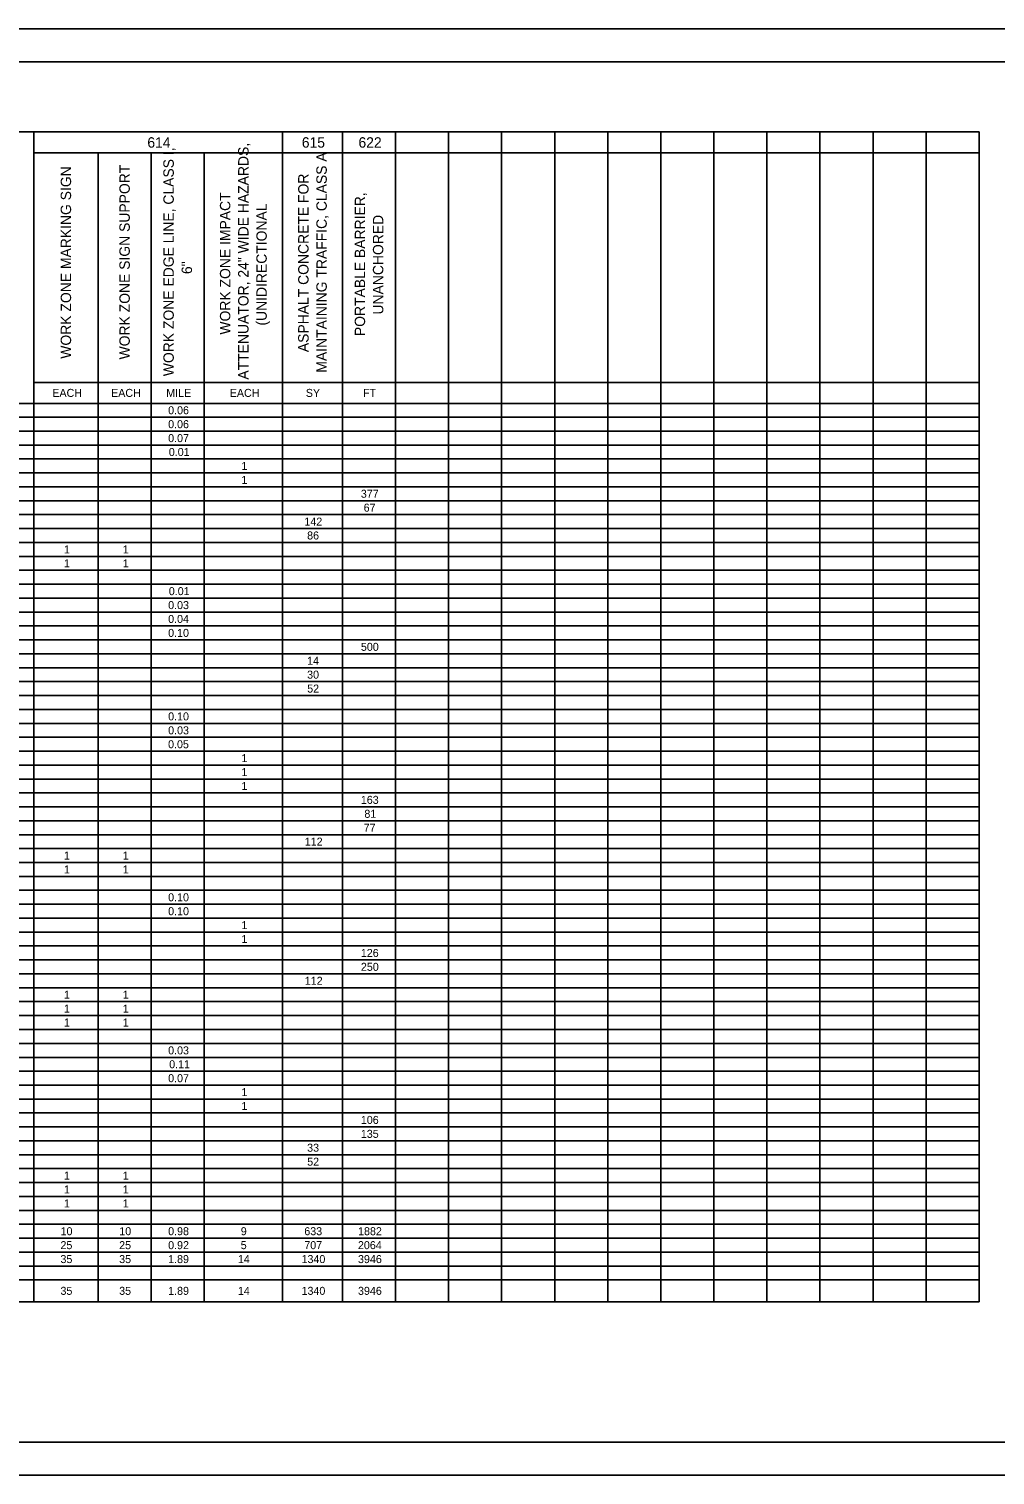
# Model space of a CAD drawing. Extents: x 0 to 37.7, y 0 to 22.
# Drawn here: x 13.5 to 28.19, y 0 to 22 of the extents above; entities that cross this region are included whole.
import ezdxf

# ---------------------------------------------------------------- set-up
doc = ezdxf.new("R2010")
doc.units = 0
for name, color, linetype in [('SH_Border', 7, 'Continuous'), ('SH_Cut_Line', 7, 'Continuous'), ('SH_Text', 7, 'Continuous')]:
    doc.layers.add(name, color=color, linetype=linetype)

msp = doc.modelspace()

# ---------------------------------------------------------------- linework, layer by layer
at = {"layer": 'SH_Border'}
msp.add_lwpolyline([(1.5, 21.5), (33.5, 21.5), (33.5, 0.5), (1.5, 0.5)], close=True, dxfattribs=at)
at = {"layer": 'SH_Cut_Line'}
msp.add_lwpolyline([(0, 0), (34, 0), (34, 22), (0, 22)], close=True, dxfattribs=at)
at = {"layer": 'SH_Text'}
for p, q in [((6.664, 20.432), (27.951, 20.432)), ((13.57, 20.432), (13.57, 2.638)), ((17.354, 20.432), (17.354, 2.638)), ((18.267, 20.432), (18.267, 2.638)), ((19.074, 20.432), (19.074, 2.638)), ((19.881, 20.432), (19.881, 2.638)), ((20.688, 20.432), (20.688, 2.638)), ((21.495, 20.432), (21.495, 2.638)), ((22.302, 20.432), (22.302, 2.638)), ((23.109, 20.432), (23.109, 2.638)), ((23.916, 20.432), (23.916, 2.638)), ((24.723, 20.432), (24.723, 2.638)), ((25.53, 20.432), (25.53, 2.638)), ((26.337, 20.432), (26.337, 2.638)), ((27.144, 20.432), (27.144, 2.638)), ((27.951, 20.432), (27.951, 2.638)), ((13.57, 20.115), (27.951, 20.115)), ((14.549, 20.115), (14.549, 2.638)), ((15.357, 20.115), (15.357, 2.638)), ((16.164, 20.115), (16.164, 2.638)), ((13.57, 16.622), (27.951, 16.622)), ((6.664, 16.304), (27.951, 16.304)), ((6.664, 16.093), (27.951, 16.093)), ((6.664, 15.881), (27.951, 15.881)), ((6.664, 15.669), (27.951, 15.669)), ((6.664, 15.458), (27.951, 15.458)), ((6.664, 15.246), (27.951, 15.246)), ((6.664, 15.034), (27.951, 15.034)), ((6.664, 14.823), (27.951, 14.823)), ((6.664, 14.611), (27.951, 14.611)), ((6.664, 14.399), (27.951, 14.399)), ((6.664, 14.188), (27.951, 14.188)), ((6.664, 13.976), (27.951, 13.976)), ((6.664, 13.764), (27.951, 13.764)), ((6.664, 13.553), (27.951, 13.553)), ((6.664, 13.341), (27.951, 13.341)), ((6.664, 13.129), (27.951, 13.129)), ((6.664, 12.918), (27.951, 12.918)), ((6.664, 12.706), (27.951, 12.706)), ((6.664, 12.494), (27.951, 12.494)), ((6.664, 12.282), (27.951, 12.282)), ((6.664, 12.071), (27.951, 12.071)), ((6.664, 11.859), (27.951, 11.859)), ((6.664, 11.647), (27.951, 11.647)), ((6.664, 11.436), (27.951, 11.436)), ((6.664, 11.224), (27.951, 11.224)), ((6.664, 11.012), (27.951, 11.012)), ((6.664, 10.801), (27.951, 10.801)), ((6.664, 10.589), (27.951, 10.589)), ((6.664, 10.377), (27.951, 10.377)), ((6.664, 10.166), (27.951, 10.166)), ((6.664, 9.954), (27.951, 9.954)), ((6.664, 9.742), (27.951, 9.742)), ((6.664, 9.531), (27.951, 9.531)), ((6.664, 9.319), (27.951, 9.319)), ((6.664, 9.107), (27.951, 9.107)), ((6.664, 8.896), (27.951, 8.896)), ((6.664, 8.684), (27.951, 8.684)), ((6.664, 8.472), (27.951, 8.472)), ((6.664, 8.261), (27.951, 8.261)), ((6.664, 8.049), (27.951, 8.049)), ((6.664, 7.837), (27.951, 7.837)), ((6.664, 7.626), (27.951, 7.626)), ((6.664, 7.414), (27.951, 7.414)), ((6.664, 7.202), (27.951, 7.202)), ((6.664, 6.99), (27.951, 6.99)), ((6.664, 6.779), (27.951, 6.779)), ((6.664, 6.567), (27.951, 6.567)), ((6.664, 6.355), (27.951, 6.355)), ((6.664, 6.144), (27.951, 6.144)), ((6.664, 5.932), (27.951, 5.932)), ((6.664, 5.72), (27.951, 5.72)), ((6.664, 5.509), (27.951, 5.509)), ((6.664, 5.297), (27.951, 5.297)), ((6.664, 5.085), (27.951, 5.085)), ((6.664, 4.874), (27.951, 4.874)), ((6.664, 4.662), (27.951, 4.662)), ((6.664, 4.45), (27.951, 4.45)), ((6.664, 4.239), (27.951, 4.239)), ((6.664, 4.027), (27.951, 4.027)), ((6.664, 3.815), (27.951, 3.815)), ((6.664, 3.604), (27.951, 3.604)), ((6.664, 3.392), (27.951, 3.392)), ((6.664, 3.18), (27.951, 3.18)), ((6.664, 2.969), (27.951, 2.969)), ((6.664, 2.638), (27.951, 2.638))]:
    msp.add_line(p, q, dxfattribs=at)

# ---------------------------------------------------------------- texts
for s, height, p in [('614', 0.1582, (15.299, 20.194)), ('615', 0.1582, (17.648, 20.194)), ('622', 0.1582, (18.51, 20.194)), ('EACH', 0.1217, (13.853, 16.402)), ('EACH', 0.1217, (14.747, 16.402)), ('MILE', 0.1217, (15.586, 16.402)), ('EACH', 0.1217, (16.552, 16.402)), ('SY', 0.1217, (17.709, 16.402)), ('FT', 0.1217, (18.579, 16.402)), ('0.06', 0.1217, (15.615, 16.138)), ('0.06', 0.1217, (15.615, 15.926)), ('0.07', 0.1217, (15.615, 15.714)), ('0.01', 0.1217, (15.625, 15.503)), ('1', 0.122, (16.73, 15.291)), ('1', 0.122, (16.73, 15.079)), ('377', 0.1217, (18.546, 14.868)), ('67', 0.1217, (18.589, 14.656)), ('142', 0.1217, (17.687, 14.444)), ('86', 0.1217, (17.729, 14.233)), ('1', 0.122, (14.031, 14.021)), ('1', 0.122, (14.925, 14.021)), ('1', 0.122, (14.031, 13.809)), ('1', 0.122, (14.925, 13.809)), ('0.01', 0.1217, (15.625, 13.386)), ('0.03', 0.1217, (15.615, 13.174)), ('0.04', 0.1217, (15.615, 12.963)), ('0.10', 0.1217, (15.615, 12.751)), ('500', 0.1217, (18.547, 12.539)), ('14', 0.1217, (17.729, 12.327)), ('30', 0.1217, (17.729, 12.116)), ('52', 0.1217, (17.73, 11.904)), ('0.10', 0.1217, (15.615, 11.481)), ('0.03', 0.1217, (15.615, 11.269)), ('0.05', 0.1217, (15.614, 11.057)), ('1', 0.122, (16.73, 10.846)), ('1', 0.122, (16.73, 10.634)), ('1', 0.122, (16.73, 10.422)), ('163', 0.1217, (18.546, 10.211)), ('81', 0.1217, (18.6, 9.999)), ('77', 0.1217, (18.589, 9.787)), ('112', 0.1217, (17.693, 9.576)), ('1', 0.122, (14.031, 9.364)), ('1', 0.122, (14.925, 9.364)), ('1', 0.122, (14.031, 9.152)), ('1', 0.122, (14.925, 9.152)), ('0.10', 0.1217, (15.615, 8.729)), ('0.10', 0.1217, (15.615, 8.517)), ('1', 0.122, (16.73, 8.306)), ('1', 0.122, (16.73, 8.094)), ('126', 0.1217, (18.546, 7.882)), ('250', 0.1217, (18.547, 7.671)), ('112', 0.1217, (17.693, 7.459)), ('1', 0.122, (14.031, 7.247)), ('1', 0.122, (14.925, 7.247)), ('1', 0.122, (14.031, 7.035)), ('1', 0.122, (14.925, 7.035)), ('1', 0.122, (14.031, 6.824)), ('1', 0.122, (14.925, 6.824)), ('0.03', 0.1217, (15.615, 6.4)), ('0.11', 0.1217, (15.631, 6.189)), ('0.07', 0.1217, (15.615, 5.977)), ('1', 0.122, (16.73, 5.765)), ('1', 0.122, (16.73, 5.554)), ('106', 0.1217, (18.546, 5.342)), ('135', 0.1217, (18.546, 5.13)), ('33', 0.1217, (17.729, 4.919)), ('52', 0.1217, (17.73, 4.707)), ('1', 0.122, (14.031, 4.495)), ('1', 0.122, (14.031, 4.284)), ('1', 0.122, (14.925, 4.495)), ('1', 0.122, (14.925, 4.284)), ('1', 0.122, (14.031, 4.072)), ('1', 0.122, (14.925, 4.072)), ('10', 0.1217, (13.979, 3.649)), ('10', 0.1217, (14.872, 3.649)), ('0.98', 0.1217, (15.615, 3.649)), ('9', 0.122, (16.72, 3.649)), ('633', 0.1217, (17.686, 3.649)), ('1882', 0.1217, (18.504, 3.649)), ('25', 0.1217, (13.977, 3.437)), ('25', 0.1217, (14.87, 3.437)), ('0.92', 0.1217, (15.615, 3.437)), ('5', 0.122, (16.719, 3.437)), ('707', 0.1217, (17.686, 3.437)), ('2064', 0.1217, (18.502, 3.437)), ('35', 0.1217, (13.977, 3.225)), ('35', 0.1217, (14.87, 3.225)), ('1.89', 0.1217, (15.615, 3.225)), ('14', 0.1217, (16.676, 3.225)), ('1340', 0.1217, (17.644, 3.225)), ('3946', 0.1217, (18.503, 3.225)), ('35', 0.1217, (13.977, 2.742)), ('35', 0.1217, (14.87, 2.742)), ('1.89', 0.1217, (15.615, 2.742)), ('14', 0.1217, (16.676, 2.742)), ('1340', 0.1217, (17.644, 2.742)), ('3946', 0.1217, (18.503, 2.742))]:
    msp.add_text(s, height=height, dxfattribs=at).set_placement(p)
for s, height, p in [('ATTENUATOR, 24" WIDE HAZARDS, ', 0.15823, (16.838, 16.665)), ('WORK ZONE EDGE LINE, CLASS I, ', 0.15823, (15.701, 16.717)), ('MAINTAINING TRAFFIC, CLASS A', 0.15823, (18.028, 16.771)), ('WORK ZONE MARKING SIGN', 0.15823, (14.139, 16.983)), ('WORK ZONE SIGN SUPPORT', 0.15823, (15.032, 16.972)), ('ASPHALT CONCRETE FOR ', 0.15823, (17.751, 17.083)), ('WORK ZONE IMPACT ', 0.15823, (16.561, 17.35)), ('PORTABLE BARRIER, ', 0.15823, (18.611, 17.327)), ('(UNIDIRECTIONAL', 0.15823, (17.115, 17.487)), ('UNANCHORED', 0.1582, (18.888, 17.655)), ('6"', 0.1582, (15.978, 18.271))]:
    msp.add_text(s, height=height, rotation=90, dxfattribs=at).set_placement(p)

doc.saveas('drawing.dxf')
